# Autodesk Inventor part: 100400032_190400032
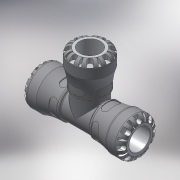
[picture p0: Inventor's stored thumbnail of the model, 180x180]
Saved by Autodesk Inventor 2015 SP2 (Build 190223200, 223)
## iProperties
Created: 2016-12
Part Number: 100400032_190400032
Material: Generic
Description: PLASSON TEE 32X32X32 SERIES 1
Document SubType Name: Modeling
Designer: KIM
Mass: 664.223 g
Surface Area: 733.008 cm^2
Volume: 474.445 cm^3
Density: 1 g/cm^3
Appearance: Default
Author: KIM
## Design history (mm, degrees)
derived "1004.ipt"
feature "Solid1::1004.ipt"
tag "TaggingFeature1"
body "Solid1"
other parameters: "d1" = 22.68, "d2" = 32, "d4" = 58, "d8" = 49.3, "d13" = 7.2, "d14" = 7.2, "d15" = 0, "d17" = 360 deg, "d19" = 8 deg, "d20" = 0.64, "d21" = 0.64, "d22" = 8 deg, "d24" = 0, "d26" = 360 deg, "d33" = 5.8, "d43" = 45.24, "d51" = 0.58, "d54" = 11.2, "d55" = 7.04, "d57" = 14.112, "d58" = 0, "d74" = 0, "d77" = 2.66667, "d78" = 54, "d79" = 45.24, "d80" = 152, "d82" = 0.64, "d115" = 360 deg, "d139" = 7.2, "d140" = 0, "d142" = 360 deg, "d207" = 90 deg, "d209" = 22.68, "d210" = 32, "d212" = 58, "d213" = 49.3, "d215" = 45.24, "d216" = 2.66667, "d217" = 54, "d225" = 84, "d226" = 54, "d228" = 9.52, "d229" = 7.2, "d233" = 7.2, "d234" = 0, "d236" = 360 deg, "d238" = 8 deg, "d239" = 8 deg, "d240" = 0.64, "d241" = 0.64, "d243" = 0, "d245" = 360 deg, "d247" = 1.16, "d248" = 3.24, "d249" = 3.24, "d250" = 9.52, "d252" = 11.2, "d253" = 7.36, "d254" = 14.112, "d255" = 0, "d257" = 360 deg, "d259" = 0.64, "d261" = 0, "d262" = 1.16, "d264" = 0, "d266" = 0, "d267" = 0.58, "d_" = 32, "E_" = 58, "l_" = 54, "A_" = 84, "H_" = 152, "d9" = 9, "d11" = 58, "d230" = 58, "d232" = 9
